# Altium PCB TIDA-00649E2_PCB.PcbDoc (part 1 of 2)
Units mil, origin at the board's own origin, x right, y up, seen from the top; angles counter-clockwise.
Board outline 3905 x 2600 mil, 2 copper layers (Top Layer, Bottom Layer), stack 62 mil thick; 120 components, 45 nets, 260 pads, 117 vias.
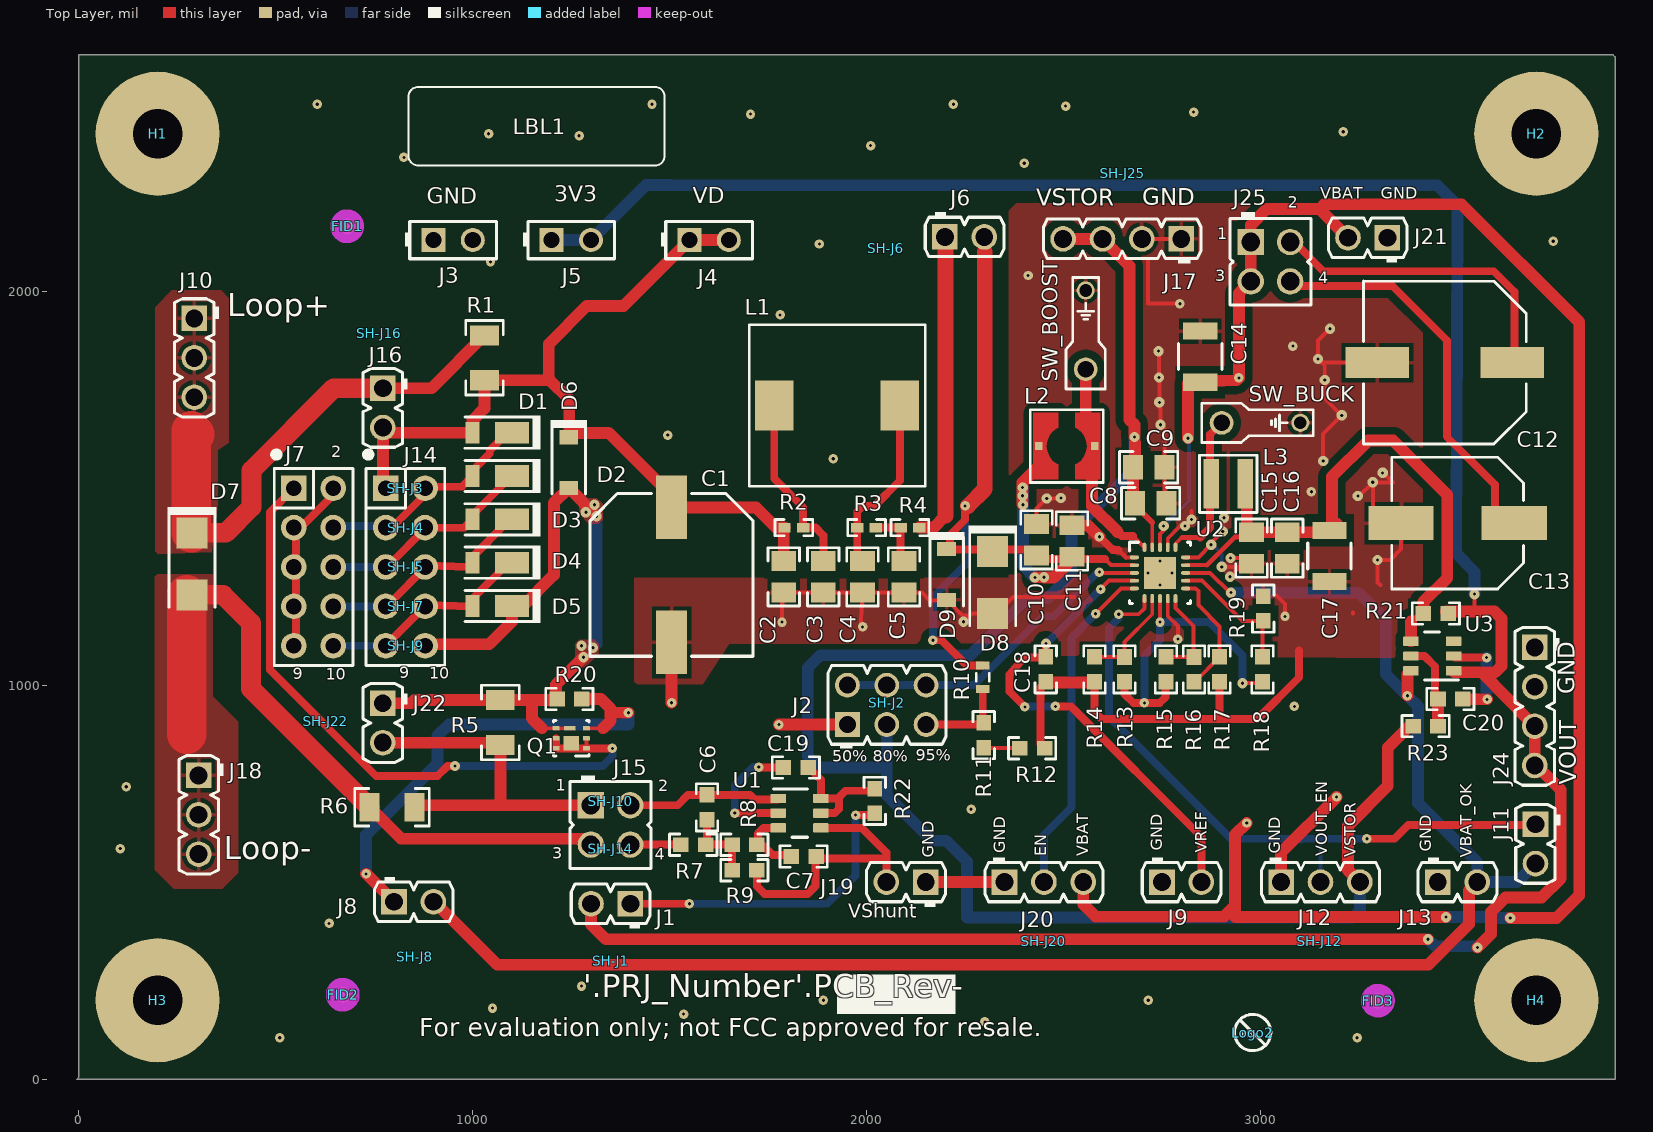
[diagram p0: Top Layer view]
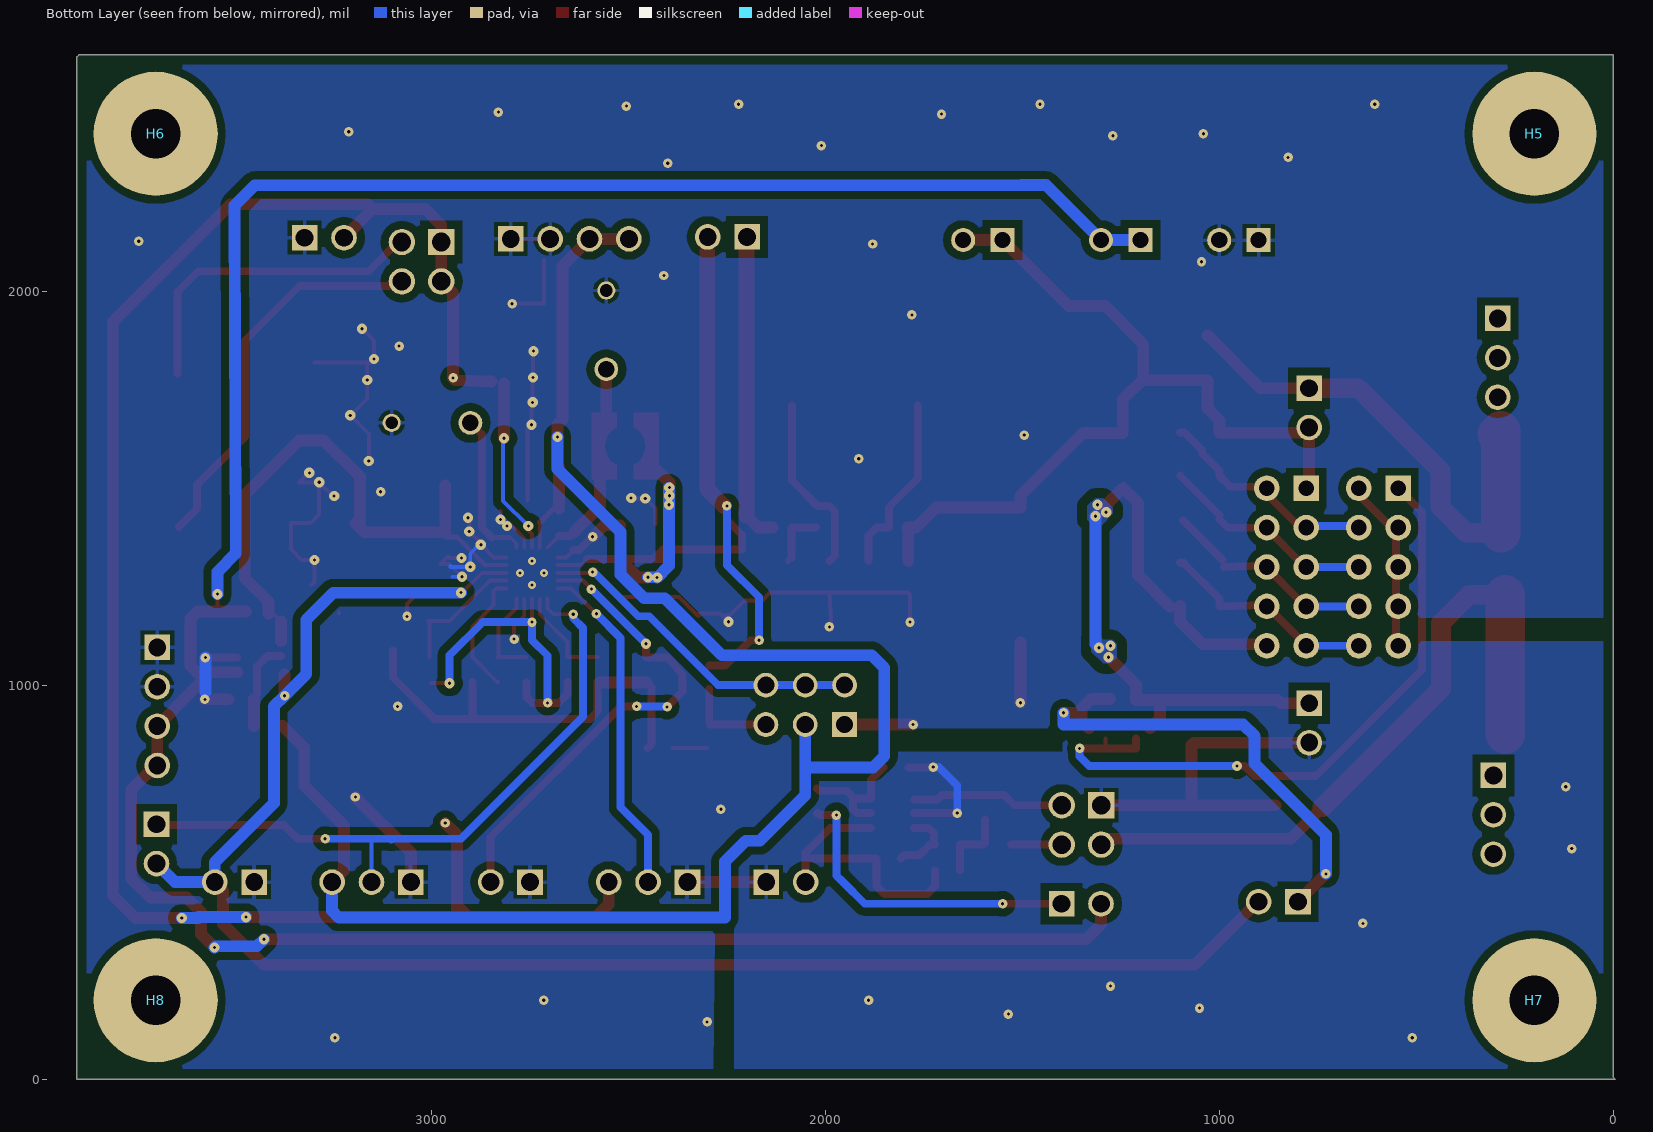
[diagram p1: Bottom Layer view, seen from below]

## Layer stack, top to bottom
Top Solder: solder mask 0.4, Solder Resist, Dk 3.5
Top Layer: signal copper 1.4
Dielectric1: core 59.2, FR-4, Dk 4.8
Bottom Layer: signal copper 1.4
Bottom Solder: solder mask 0.4, Solder Resist, Dk 3.5

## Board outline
-5,0 3900,0 3900,2595 3895,2600 0,2600 0,5 -5,0

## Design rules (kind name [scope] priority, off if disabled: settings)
AcuteAngle [All] p1: minimum=4.50000000000000E+0001 checktracksonly=FALSE
AssemblyTestPointUsage [All] p1: valid=2
BoardOutlineClearance BoardOutlineClearance_MountingHoles [OnCopper and InComponentClass('Mounting Holes')] p1: gap=40
BoardOutlineClearance BoardOutlineClearance_Poly [OnCopper and IsPoly] p2: gap=25
BoardOutlineClearance [OnCopper and Not InComponentClass('Logo') and not InComponentClass('FiducialMark') and not InRegion(1000,500,4000,800) and not InPoly] p3: gap=75
Clearance Clearance_Keepouts [((IsTrack Or IsArc) And Not InPoly) And IsFree and IsKeepOut vs ((IsTrack Or IsArc) And Not InPoly) And IsFree and IsKeepOut] p1: gap=0
Clearance Clearance_Poly [InPolygon] p2: gap=25 except(20: Track-Poly SMDPad-Poly THPad-Poly Via-Poly)
Clearance [All] p3: gap=7.87
ComponentClearance ComponentClearance_MountingHoles_FiducialMarks [InComponentClass('Mounting Holes') vs InComponentClass('FiducialMark')] p1: gap=50 collisioncheckmode=3 verticalgap=10 showdistances=FALSE
ComponentClearance ComponentClearance_Shunt [InComponentClass('Header') OR InComponentClass('Shunt') vs InComponentClass('Shunt')] p2: gap=0 collisioncheckmode=3 verticalgap=0 showdistances=FALSE
ComponentClearance ComponentClearance_Logo [InComponentClass('Logo')] p3: gap=50 collisioncheckmode=3 verticalgap=10 showdistances=FALSE
ComponentClearance ComponentClearance_ScrewToNut [(HasFootprint('NY PMS 440 0025 PH')) vs (HasFootprint('Keystone_1902C'))] p4: gap=5 collisioncheckmode=3 verticalgap=10 showdistances=FALSE
ComponentClearance ComponentClearance_MountingHoles [InComponentClass('Mounting Holes')] p5: gap=100 collisioncheckmode=3 verticalgap=10 showdistances=FALSE
ComponentClearance ComponentClearance_SmallPassives [HasFootprint('0201*') or HasFootprint('0402*') or HasFootprint('0508') or HasFootprint('0603*') or HasFootprint('0612') or HasFootprint('0805*') or HasFootprint('0815*') or HasFootprint('0830*') or HasFootprint('1206*') or HasFootprint('1210*') or HasFootprint('1808*') or HasFootprint('1812*') or HasFootprint('1825*') or HasFootprint('2010*') or HasFootprint('2220*') or HasFootprint('2225*') or HasFootprint('2512*') or HasFootprint('2728*') or HasFootprint('3518*') vs HasFootprint('0201*') or HasFootprint('0402*') or HasFootprint('0508') or HasFootprint('0603*') or HasFootprint('0612') or HasFootprint('0805*') or HasFootprint('0815*') or HasFootprint('0830*') or HasFootprint('1206*') or HasFootprint('1210*') or HasFootprint('1808*') or HasFootprint('1812*') or HasFootprint('1825*') or HasFootprint('2010*') or HasFootprint('2220*') or HasFootprint('2225*') or HasFootprint('2512*') or HasFootprint('2728*') or HasFootprint('3518*')] p6: gap=14.96 collisioncheckmode=3 verticalgap=10 showdistances=FALSE
ComponentClearance ComponentClearance_THtoSMT [IsThruComponent vs IsSMTComponent] p7: gap=0 collisioncheckmode=3 verticalgap=0 showdistances=FALSE
ComponentClearance ComponentClearance_THtoTH [IsThruComponent vs IsThruComponent] p8: gap=0 collisioncheckmode=3 verticalgap=0 showdistances=FALSE
ComponentClearance [All] p9: gap=0 collisioncheckmode=3 verticalgap=0 showdistances=FALSE
DiffPairsRouting [All] p1: maxlimit=100 minlimit=10 mostfreqgap=10 toplayer_minwidth=15 toplayer_maxwidth=15 toplayer_prefwidth=15 bottomlayer_minwidth=15 bottomlayer_maxwidth=15 bottomlayer_prefwidth=15 maxuncoupledlength=1000
FabricationTestPointUsage TestPointUsage [All] p1: valid=2 allowmultiple=FALSE
FabricationTestpoint Testpoint [All] p1: side=3 testpointundercomponent=TRUE minsize=40 maxsize=100 preferedsize=60 minholesize=0 maxholesize=40 preferedholesize=32 testpointgrid=1 allowsidetop=TRUE allowsidebottom=TRUE usegrid=TRUE gridtolerance=0.01
FanoutControl Fanout_LCC [IsLCC] p1: bgadir=Out bgaviamode=Centered fanoutstyle=Auto fanoutdirection=Alternating viagrid=1 // Fanout_LCC (Default Rule)
FanoutControl Fanout_BGA [IsBGA] p2: bgadir=Out bgaviamode=Centered fanoutstyle=Auto fanoutdirection=Alternating viagrid=1 // Fanout_BGA (Default Rule)
FanoutControl Fanout_Default [All] p4: bgadir=Out bgaviamode=Centered fanoutstyle=Auto fanoutdirection=Alternating viagrid=1 // Fanout_Default (Default Rule)
FanoutControl Fanout_Small [(CompPinCount < 5)] p5: bgadir=Out bgaviamode=Centered fanoutstyle=Auto fanoutdirection=OutThenIn viagrid=1 // Fanout_Small (Default Rule)
HoleSize [All] p1: absolutevalues=TRUE maxlimit=251 minlimit=7.87 maxpercent=80.000 minpercent=20.000
MinimumAnnularRing MinimumAnnularRing_ThermalPadVias [IsVia and InAnyComponent] p1: minimumring=5.91
MinimumAnnularRing [All] p2: minimumring=8
MinimumSolderMaskSliver MinimumSolderMaskSliver_Logo [InComponentClass('Logo') vs InComponentClass('Logo')] p1: minsoldermaskwidth=0.7
MinimumSolderMaskSliver [All] p2: minsoldermaskwidth=3.94
PlaneConnect [All] p1: planeconnectstyle=Direct reliefexpansion=10 reliefentries=4 reliefconductorwidth=10 reliefairgap=10
PolygonConnect PolygonConnect_2 [HasFootprint('SMA')] p1: connectstyle=Direct reliefconductorwidth=10 reliefentries=4 polygonreliefangle="90 Angle" airgapwidth=10
PolygonConnect PolygonConnect_1_via [isvia] p2: connectstyle=Direct reliefconductorwidth=10 reliefentries=4 polygonreliefangle="90 Angle" airgapwidth=10
PolygonConnect PolygonConnect_1 [All] p3: connectstyle=Relief reliefconductorwidth=10 reliefentries=4 polygonreliefangle="90 Angle" airgapwidth=10
PolygonConnect [InNet('LOOP +')] p4: connectstyle=Relief reliefconductorwidth=30 reliefentries=4 polygonreliefangle="90 Angle" airgapwidth=10
RoutingVias ThermalPadVias [IsVia and InAnyComponent] p1: holewidth=7.87 width=19.68 viastyle="Through Hole" minholewidth=7.87 minwidth=19.68 maxholewidth=12.99 maxwidth=23.62
RoutingVias [All] p2: holewidth=8 width=24 viastyle="Through Hole" minholewidth=8 minwidth=24 maxholewidth=40 maxwidth=65
SilkToBoardRegionClearance [Not ((IsComment or IsDesignator) And (Hide <> 'False')) and not InRegion(1000,500,4000,800)] p1:
SilkToSilkClearance SilkToSilkClearance_Pb-FreeLogo [(HasFootprint('Pb-Free_Overlay_Medium') OR HasFootprint('Pb-Free_Overlay_Small')) vs (HasFootprint('Pb-Free_Overlay_Medium') OR HasFootprint('Pb-Free_Overlay_Small'))] p1: silktosilkclearance=0
SilkToSilkClearance [All] p2: silktosilkclearance=4
SilkToSolderMaskClearance SilkToComponentPadClearance [IsPad and InAnycomponent] p1: minsilkscreentomaskgap=5 clearancetoexposedcopper=TRUE
SilkToSolderMaskClearance "Silk to Solder Mask Opening" [All] p2: minsilkscreentomaskgap=4 clearancetoexposedcopper=FALSE
SolderMaskExpansion [All] p1: expansion=1.97
Width [All] p1: maxlimit=100 minlimit=6 preferedwidth=10 checkconnectedcopper=TRUE
15 further rules are at their usual default settings.

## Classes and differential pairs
component class TIDA-00649E2_Boost: C8 C9 C10 C11 C12 C13 C14 C15 C16 C17 C18 C20 D8 D9 J2 J6 J9 J11 J12 J13 J17 J20 J21 J24 J25 L2 L3 R10 R11 R12 R13 R14 R15 R16 R17 R18 R19 R21 R23 SH-J2 SH-J6 SH-J12 SH-J20 SH-J25 SW_BOOST SW_BUCK U2 U3
component class Header: J1 J2 J6 J7 J8 J9 J10 J11 J12 J13 J14 J15 J16 J17 J18 J19 J20 J21 J22 J24 J25
component class "Mounting Holes": H1 H2 H3 H4
component class TIDA-00649E2_EVM_Hardware: FID1 FID2 FID3 H1 H2 H3 H4 H5 H6 H7 H8 LBL1 Logo2 Logo3 ZZ1 ZZ2 ZZ3 ZZ4 ZZ5
component class FiducialMark: FID1 FID2 FID3
component class AssemblyNote: ZZ1 ZZ2 ZZ3 ZZ4 ZZ5
component class Label: LBL1
component class TIDA-00649E2_DiodeVoltage: C1 C2 C3 C4 C5 C6 C7 C19 D1 D2 D3 D4 D5 D6 D7 J1 J3 J4 J5 J7 J8 J10 J14 J15 J16 J18 J19 J22 L1 Q1 R1 R2 R3 R4 R5 R6 R7 R8 R9 R20 R22 SH-J1 SH-J3 SH-J4 SH-J5 SH-J7 SH-J8 SH-J9 SH-J10 SH-J14 SH-J16 SH-J22 U1

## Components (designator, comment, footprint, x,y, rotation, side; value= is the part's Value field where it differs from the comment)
C1 "EEEFPE561UAP" Panasonic_G 1504.68,1280 r270 top
C2 "GRM21BR60J107M" 0805_HV 1789.68,1275 r270 top
C3 "GRM21BR61A106KE19L" 0805_HV 1889.68,1275 r270 top
C4 "GRM21BR61A106KE19L" 0805_HV 1989.68,1275 r270 top
C5 "GRM21BR61A106KE19L" 0805_HV 2094.68,1275 r270 top
C6 "C0603C102J5GAC" 0603 1594.68,690 r270 top
C7 "C0603C151J5GACTU" 0603 1840,565 r180 top
C8 "C0805C104K4RACTU" 0805_HV 2721,1462 r0 top
C9 "LMK212B7475KG-T" 0805_HV 2716,1553 r0 top
C10 "C0805C475K8PACTU" 0805_HV 2431,1369 r90 top
C11 "C0805C104K4RACTU" 0805_HV 2521,1366 r90 top
C12 "EEE-FC1A102P" SM_RADIAL_G 3468,1819 r180 top
C13 "APXE100ARA221MH70G" CAPSMT_62_H70 3501,1412 r180 top
C14 "C1210C107M8PACTU" 1210_280 2847,1834 r270 top
C15 "JMK212BJ226MG-T" 0805_HV 2977,1348 r270 top
C16 "GRM21BR71A475KA73L" 0805_HV 3068,1348 r270 top
C17 "C1210C107M8PACTU" 1210_280 3175,1328 r90 top
C18 "GRM188R71H103KA01D" 0603 2454.68,1040 r270 top
C19 "885012206046" 0603 1820.13,791.14 r0 top
C20 "885012206046" 0603 3482,965 r0 top
D1 "DFLS1200-7" PowerDI123 1049.68,1641 r180 top
D2 "DFLU1200-7" PowerDI123 1049.68,1531 r180 top
D3 "DFLU1200-7" PowerDI123 1049.68,1421 r180 top
D4 "DFLU1200-7" PowerDI123 1049.68,1311 r180 top
D5 "DFLU1200-7" PowerDI123 1049.68,1201 r180 top
D6 "1N5819HW-7-F" SOD-123 1243.68,1565 r270 top
D7 "SMAJ5.0A-TR" SMA 287,1308 r270 top
D8 "SMAJ5.0A-TR" SMA 2320,1261 r270 top
D9 "1N5819HW-7-F" SOD-123 2203,1281 r270 top
FID1 "Fiducial" Fiducial10-20 681,2165 r0 top
FID2 "Fiducial" Fiducial10-20 670,214 r0 top
FID3 "Fiducial" Fiducial10-20 3298,199 r0 top
H1 "NY PMS 440 0025 PH" "NY PMS 440 0025 PH" 200,2400 r0 top locked
H2 "NY PMS 440 0025 PH" "NY PMS 440 0025 PH" 3700,2400 r0 top locked
H3 "NY PMS 440 0025 PH" "NY PMS 440 0025 PH" 200,200 r0 top locked
H4 "NY PMS 440 0025 PH" "NY PMS 440 0025 PH" 3700,200 r0 top locked
H5 "1902C" Keystone_1902C 200,2400 r180 bottom locked
H6 "1902C" Keystone_1902C 3700,2400 r180 bottom locked
H7 "1902C" Keystone_1902C 200,200 r180 bottom locked
H8 "1902C" Keystone_1902C 3700,200 r180 bottom locked
J1 "61300211121" WURTH_61300211121 1350,445 r180 top
J2 "61300621121" Wurth_61300621121 2050.98,950 r90 top
J3 "SSW-102-01-T-S" Samtec_SSW-102-01-x-S 950,2130 r0 top
J4 "SSW-102-01-T-S" Samtec_SSW-102-01-x-S 1600,2130 r0 top
J5 "SSW-102-01-T-S" Samtec_SSW-102-01-x-S 1250,2130 r0 top
J6 "61300211121" WURTH_61300211121 2248.68,2138 r0 top
J7 "PEC05DAAN" CONN_PEC05DAAN 595.68,1300 r270 top
J8 "61300211121" WURTH_61300211121 850,450 r0 top
J9 "61300211121" WURTH_61300211121 2799.68,500 r0 top
J10 "61300311121" WURTH_61300311121 293,1831 r270 top
J11 "61300211121" WURTH_61300211121 3698,597 r270 top
J12 "61300311121" WURTH_61300311121 3152.2,500 r0 top
J13 "61300211121" WURTH_61300211121 3500,500 r0 top
J14 "PEC05DAAN" CONN_PEC05DAAN 829,1300 r270 top
J15 "PBC02DAAN" Sullins_PxC02DAAN 1349.68,645 r0 top
J16 "61300211121" WURTH_61300211121 771.68,1704 r270 top
J17 "61300411121" WURTH_61300411121 2648.68,2133 r180 top
J18 "61300311121" WURTH_61300311121 304,671 r270 top
J19 "61300211121" WURTH_61300211121 2100,500 r180 top
J20 "61300311121" WURTH_61300311121 2450,500 r0 top
J21 "61300211121" WURTH_61300211121 3272,2136 r180 top
J22 "61300211121" WURTH_61300211121 771.37,904 r270 top
J24 "61300411121" WURTH_61300411121 3696,946 r270 top
J25 "PBC02DAAN" Sullins_PxC02DAAN 3025,2075 r0 top
L1 "SLF10145T-152MR22-PF" SLF10145 1924.68,1710 r0 top
L2 "744031220" WE-TPC-S 2508,1607 r0 top
L3 "744029100" WE-TPC_2813 2918,1511 r0 top
LBL1 "Size: 0.65\" x 0.20 \"" Label_650x200 1162,2419 r0 top
Logo2 "Pb-Free Symbol" Pb-Free_Overlay_Small 2980,118 r0 top
Logo3 "FCC disclaimer" FCC_disclaimer 2495,3410 r0 top
Q1 "CSD17313Q2" DQK0006C 1250,865 r180 top
R1 "CRCW120610R0FKEA" 1206 1029.68,1831 r90 top
R2 "CRCW04023R32FKED" 0402 1815,1400 r0 top
R3 "CRCW04023R32FKED" 0402 1999.68,1400 r0 top
R4 "CRCW04023R32FKED" 0402 2109.68,1400 r0 top
R5 "CRCW120610R0FKEA" 1206 1070,905 r90 top
R6 "CRCW120610R0FKEA" 1206 795,690 r0 top
R7 "RC0603FR-075K76L" 0603 1559.68,595 r0 top
R8 "CRCW06035K23FKEA" 0603 1689.68,595 r0 top
R9 "CRCW060357K6FKEA" 0603 1689.68,530 r0 top
R10 "CRCW06031M02FKEA" 0603S 2294.68,1020 r270 top
R11 "CRCW060310M0FKEA" 0603 2297,873 r90 top
R12 "CRCW06038M87FKEA" 0603 2420,840 r0 top
R13 "CRCW06037M50FKEA" 0603 2654.68,1040 r90 top
R14 "CRCW06035M76FKEA" 0603 2578.18,1040 r270 top
R15 "CRCW060373K2FKEA" 0603 2760,1040 r270 top
R16 "CRCW06037M68FKEA" 0603 2831.19,1040 r90 top
R17 "CRCW06034M42FKEA" 0603 2896,1040 r90 top
R18 "CRCW06038M25FKEA" 0603 3005,1040 r270 top
R19 "CRCW06034M75FKEA" 0603 3007,1194.5 r270 top
R20 "CRCW06031M00FKEA" 0603 1245.31,965 r0 top
R21 "MCR03EZPJ000" 0603 3445,1182 r0 top
R22 "CRCW060310R0FKEA" 0603 2020.73,705.98 r270 top
R23 "CRCW060310R0FKEA" 0603 3419,896 r0 top
SH-J1 "60900213421" Wurth_60900213421 1350,300 r0 top
SH-J2 "60900213421" Wurth_60900213421 2050.98,955 r90 top
SH-J3 "60900213421" Wurth_60900213421 829,1500 r0 top
SH-J4 "60900213421" Wurth_60900213421 830,1400 r0 top
SH-J5 "60900213421" Wurth_60900213421 830,1300 r0 top
SH-J6 "60900213421" Wurth_60900213421 2049,2109 r90 top
SH-J7 "60900213421" Wurth_60900213421 830,1200 r0 top
SH-J8 "60900213421" Wurth_60900213421 853,311 r0 top
SH-J9 "60900213421" Wurth_60900213421 830,1100 r0 top
SH-J10 "60900213421" Wurth_60900213421 1349.68,705 r0 top
SH-J12 "60900213421" Wurth_60900213421 3150,350 r0 top
SH-J14 "60900213421" Wurth_60900213421 1350,585 r0 top
SH-J16 "60900213421" Wurth_60900213421 762,1894 r0 top
SH-J20 "60900213421" Wurth_60900213421 2450,350 r0 top
SH-J22 "60900213421" Wurth_60900213421 627,909 r270 top
SH-J25 "60900213421" Wurth_60900213421 2650,2300 r0 top
SW_BOOST "TESTPOINT_PIGTAIL" TESTPOINT_PIGTAIL 2556,1802 r180 top
SW_BUCK "TESTPOINT_PIGTAIL" TESTPOINT_PIGTAIL 2901,1666 r90 top
U1 "TLV341AIDBVR" DBV0006A_N 1829.68,675 r0 top
U2 "BQ25570RGRR" RGR0020A 2744.68,1285 r0 top
U3 "TS5A3160DBVR" DBV0006A_N 3436,1074 r180 top
ZZ1 "This Assembly Note is for PCB labels only" AssemblyNoteLabel 245,3498 r0 top
ZZ2 "These assemblies are ESD sensitive, ESD precautions shall be observed." AssemblyNote 245,3389.11 r0 top
ZZ3 "These assemblies must be clean and free from flux and all contaminants. Use of no clean flux is not acceptable." AssemblyNote 245,3300.56 r0 top
ZZ4 "These assemblies must comply with workmanship standards IPC-A-610 Class 2, unless otherwise specified." AssemblyNote 245,3212 r0 top
ZZ5 "Place SH-J1 to J1 Pins 1-2" AssemblyNote 250,3100 r0 top

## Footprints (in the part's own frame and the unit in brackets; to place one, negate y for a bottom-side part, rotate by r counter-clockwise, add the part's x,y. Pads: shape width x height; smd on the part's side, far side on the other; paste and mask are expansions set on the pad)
0402 [mm] "0402 from SM-752 data"
  rect 0.8x0.6 smd: 1(-0.6,0) 2(0.6,0)
  silkscreen extent -1.22,-0.52 1.22,0.52, body extent -0.55,-0.3 0.55,0.3, height 0.6
0603 [mm] "0603 from SM-752 data"
  rect 1x0.95 smd: 1(-0.8,0) 2(0.8,0)
  silkscreen extent -1.52,-0.69 1.52,0.69, body extent -0.87,-0.47 0.87,0.47, height 1
0603S [mil]
  rect 20x35 smd: 1(-30,0) 2(30,0)
  silkscreen extent -10,-17 10,17, body extent -34,-19 34,19, height 39
0805_HV [mil] "0805 with 30mil clearance between pads"
  rect 50x63 smd: 1(-40,0) 2(40,0)
  silkscreen extent -74,-40 74,40, body extent -43,-29 43,29, height 57
1206 [mm] "1206 from SM-752 data"
  rect 1.3x1.85 smd: 1(-1.45,0) 2(1.45,0)
  silkscreen extent -2.4,-1.21 2.4,1.21, body extent -1.7,-0.9 1.7,0.9, height 1.35
1210_280 [mm] "SMD, 2-Leads, Body 3.6x2.8mm, Height 2.8mm"
  rect 1.1x2.2 smd: 1(-1.65,0) 2(1.65,0)
  silkscreen extent -0.84,-1.4 0.84,1.4, body extent -1.8,-1.4 1.8,1.4, height 2.8
AssemblyNote [mil] "Assembly Note"
AssemblyNoteLabel [mil] "Assembly Note for PCB Labels"
CAPSMT_62_H70 [mm] "8 x 6.7mm:  Chemi-Con H70"
  rect 4.2x2.2 smd: 1(-3.638,0.012) 2(3.662,0.012)
  silkscreen extent -4.24,-4.24 4.26,4.26, body extent -4.24,-4.24 4.26,4.26, height 7
CONN_PEC05DAAN [mm] "SULLINS"
  rect 1.65x1.65 hole 1.016 mask+0: 1(-5.08,-1.27)
  round 1.65 hole 1.016 mask+0: 2(-5.08,1.27) 3(-2.54,-1.27) 4(-2.54,1.27) 5(0,-1.27) 6(0,1.27) 7(2.54,-1.27) 8(2.54,1.27) 9(5.08,-1.27) 10(5.08,1.27)
  silkscreen extent -7.45,-2.6 6.35,2.54, body extent -6.35,-2.54 6.35,2.54, height 8.38
DBV0006A_N [mm] "SOT23, 6-Leads, Body 2.9x1.6mm, Pitch 0.95mm, Lead Span 2.8mm, IPC Medium Density"
  rrect17% 1x0.6 smd: 1(-1.375,0.95) 2(-1.375,0) 3(-1.375,-0.95) 4(1.375,-0.95) 5(1.375,0) 6(1.375,0.95)
  silkscreen extent -1.68,-1.55 0.5,1.55, body extent -1.42,-1.46 1.42,1.46, height 1.12
DQK0006C [mm] "WSON"
  rrect12% 0.9x0.86 on Top Paste: 0(0,0.325)
  rrect34% 0.7x0.29 on Top Paste: 0(0.095,-0.65)
  rrect33% 0.45x0.3 smd: 1(-0.975,0.65) 2(-0.975,0) 3(-0.975,-0.65) 4(0.975,-0.65) 5(0.975,0) 6(0.975,0.65)
  rrect33% 0.75x0.3 smd paste-0.15: 7(0.095,-0.65)
  rrect11% 1x0.95 smd paste-0.5: 8(0,0.325)
  silkscreen extent -1.15,-1.15 1.15,1.15, body extent -1,-1 1,1, height 0.82
FCC_disclaimer [mil]
Fiducial10-20 [mm]
  round 1 smd mask+0.5: 1(0,0)
  Top Layer keep-out circle w1.178: c0,0 r0.5
Keystone_1902C [mil] "Hex Standoff, 4-40 threaded, nylon"
  body extent -145,-126 146,126, height 501
Label_650x200 [mil] "Thermal Transfer Label"
  silkscreen extent -325,-100 325,100, body extent -325,-100 325,100, height 1
"NY PMS 440 0025 PH" [mm] "4-40 nylon screw and mounting hole"
  round 8 hole 3.2: 1(0,0)
  body extent -3.3,-3.3 3.3,3.3, height 2.69
Panasonic_G [mm] "SMD, 2-Leads, Dia 10mm"
  rect 4.1x2 smd: 1(-4.35,0) 2(4.35,0)
  silkscreen extent -5.25,-5.25 5.25,5.25, body extent -5.25,-5.25 5.25,5.25, height 10.51
Pb-Free_Overlay_Small [mil]
  silkscreen extent -46,-46 46,46
PowerDI123 [mm] "Diodes Inc recommended land pattern, document number DS30628 Rev. 6-2"
  rect 2.2x1.4 smd: 1(-1.275,0)
  rect 0.9x1.4 smd: 2(1.275,0)
  silkscreen extent -3.1,-1.09 1.76,1.09, body extent -2.38,-0.97 1.52,0.96, height 1
RGR0020A [mm] "QFN, 20-Leads, Body 3.5x3.5mm, Pitch 0.5mm, Thermal Pad 2.05x2.05mm, TI Recommended"
  oval 0.6x0.24 smd: 1(-1.65,1) 2(-1.65,0.5) 3(-1.65,0) 4(-1.65,-0.5) 5(-1.65,-1) 11(1.65,-1) 12(1.65,-0.5) 13(1.65,0) 14(1.65,0.5) 15(1.65,1)
  oval 0.24x0.6 smd: 6(-1,-1.65) 7(-0.5,-1.65) 8(0,-1.65) 9(0.5,-1.65) 10(1,-1.65) 16(1,1.65) 17(0.5,1.65) 18(0,1.65) 19(-0.5,1.65) 20(-1,1.65)
  rect 2.05x2.05 smd paste-1.025: 21(0,0)
  silkscreen extent -1.97,-1.97 1.97,1.97, body extent -1.83,-1.83 1.83,1.83, height 1.01
Samtec_SSW-102-01-x-S [mm] "Receptacle, 2x1, 2.54mm, TH"
  rect 1.55x1.55 hole 1.04: 1(-1.27,0)
  round 1.55 hole 1.04: 2(1.27,0)
  silkscreen extent -3.1,-1.21 2.79,1.21, body extent -2.79,-1.21 2.8,1.2, height 8.51
SLF10145 [mm]
  rect 2.5x3.2 smd: 1(-4.05,0) 2(4.05,0)
  silkscreen extent -5.66,-5.2 5.7,5.2, body extent -5.2,-5.2 5.2,5.2, height 4.8
SM_RADIAL_G [mm] "10 x 10.2mm:  Panasonic G"
  rect 4.1x2 smd: 1(-4.35,0) 2(4.35,0)
  silkscreen extent -5.25,-5.25 5.25,5.25, body extent -5.25,-5.25 5.25,5.25, height 10.5
SMA [mm] "Molded Diode, 2-Leads, Body 4.3x2.6mm, IPC Medium Density, based on OnSemi component dimensions and land pattern"
  rect 2x2 smd: 1(-2,0) 2(2,0)
  silkscreen extent -3.66,-1.57 2.79,1.57, body extent -2.6,-1.3 2.6,1.3, height 2.42
SOD-123 [mm] "On Semi recommended land pattern"
  rect 0.915x1.22 smd: 1(-1.637,0) 2(1.637,0)
  silkscreen extent -2.74,-1.17 2.03,1.17, body extent -1.93,-0.9 1.93,0.9, height 1.35
Sullins_PxC02DAAN [mm] "Header, 2.54mm, 2x2, TH"
  rect 1.7x1.7 hole 1.2: 1(-1.27,1.27)
  round 1.7 hole 1.2: 2(1.27,1.27) 3(-1.27,-1.27) 4(1.27,-1.27)
  silkscreen extent -2.61,-2.8 2.61,3.2, body extent -2.61,-2.8 2.61,2.8, height 8.58
TESTPOINT_PIGTAIL [mil] "Pigtail"
  round 60 hole 42: 1(0,0)
  round 46 hole 32: 2(0,-200)
  silkscreen extent -50,-233 50,50
WE-TPC-S [mm] "Wurth Elektronik recommended land pattern"
  rect 0.5x0.5 smd: 1(-1.8,0) 2(1.8,0)
  Top Layer region: -0.55,1.185 -0.658,1.14 -0.931,0.931 -1.14,0.658 -1.271,0.341 -1.316,0 -1.271,-0.341 -1.14,-0.658 -0.931,-0.931 -0.658,-1.14 -0.55,-1.185 -0.55,-2.15 -2.15,-2.15 -2.15,2.15 -0.55,2.15
  Top Layer region: 2.15,-2.15 0.55,-2.15 0.55,-1.185 0.658,-1.14 0.931,-0.931 1.14,-0.658 1.271,-0.341 1.316,0 1.271,0.341 1.14,0.658 0.931,0.931 0.658,1.14 0.55,1.185 0.55,2.15 2.15,2.15
  silkscreen extent -2.35,-2.35 2.35,2.35, body extent -2.05,-2.05 2.05,2.05, height 1.8
WE-TPC_2813 [mm] "Wurth Elektronik recommended land pattern"
  rect 1x3.2 smd: 1(-1.1,0) 2(1.1,0)
  silkscreen extent -1.85,-1.85 1.85,1.85, body extent -1.5,-1.5 1.5,1.5, height 1.5
Wurth_60900213421 [mil] "Shunt, 2.54mm, Black"
  round 1 on Mech3: 0(0,0)
  body extent -98,-48 98,48, height 236
WURTH_61300211121 [mm] "Header, 2.54mm, 2x1, TH"
  rect 1.65x1.65 hole 1.15: 1(-1.27,0)
  round 1.65 hole 1.15: 2(1.27,0)
  silkscreen extent -2.54,-1.27 2.54,1.6, body extent -2.54,-1.27 2.54,1.27, height 8.54
WURTH_61300311121 [mm] "Header, 2.54mm, 3x1, TH"
  rect 1.65x1.65 hole 1.15: 1(-2.54,0)
  round 1.65 hole 1.15: 2(0,0) 3(2.54,0)
  silkscreen extent -3.81,-1.27 3.81,1.6, body extent -3.81,-1.27 3.81,1.27, height 8.54
WURTH_61300411121 [mm] "Header, 2.54mm, 4x1, TH"
  rect 1.65x1.65 hole 1.15: 1(-3.81,0)
  round 1.65 hole 1.15: 2(-1.27,0) 3(1.27,0) 4(3.81,0)
  silkscreen extent -5.08,-1.27 5.08,1.6, body extent -5.08,-1.27 5.08,1.27, height 8.54
Wurth_61300621121 [mm] "Header, 2.54mm, 3x2, TH"
  rect 1.6x1.6 hole 1.1: 1(-1.27,2.54)
  round 1.6 hole 1.1: 2(1.27,2.54) 3(-1.27,0) 4(1.27,0) 5(-1.27,-2.54) 6(1.27,-2.54)
  silkscreen extent -2.8,-3.82 2.54,3.8, body extent -2.54,-3.82 2.54,3.8, height 7.27

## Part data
C1: "CAP, AL, 560 µF, 25 V, +/- 20%, 0.08 ohm, AEC-Q200 Grade 2, SMD"
C2: "CAP, CERM, 100 µF, 6.3 V, +/- 20%, X5R, 0805"
C3 C4 C5: "CAP, CERM, 10 µF, 10 V, +/- 10%, X5R, 0805"
C6: "CAP, CERM, 1000 pF, 50 V, +/- 5%, C0G/NP0, 0603"
C7: "CAP, CERM, 150 pF, 50 V, +/- 5%, C0G/NP0, 0603"
C8 C11: "CAP, CERM, 0.1 µF, 16 V, +/- 10%, X7R, 0805"
C9 C16: "CAP, CERM, 4.7 µF, 10 V, +/- 10%, X7R, 0805"
C10: "CAP, CERM, 4.7 µF, 10 V, +/- 10%, X5R, 0805"
C12: "CAP, AL, 1000 µF, 10 V, +/- 20%, 0.15 ohm, SMD"
C13: "CAP, AL, 220 µF, 10 V, +/- 20%, 0.021 ohm, SMD"
C14 C17: "CAP, CERM, 100 µF, 10 V, +/- 20%, X5R, 1210"
C15: "CAP, CERM, 22 µF, 6.3 V, +/- 20%, X5R, 0805"
C18: "CAP, CERM, 0.01 µF, 50 V, +/- 10%, X7R, 0603"
C19 C20: "CAP, CERM, 0.1 µF, 16 V, +/- 10%, X7R, 0603"
D1: "Diode, Schottky, 200 V, 1 A, PowerDI123"
D2 D3 D4 D5: "Diode, Superfast Rectifier, 200 V, 1 A, AEC-Q101, PowerDI123"
D6 D9: "Diode, Schottky, 40 V, 1 A, SOD-123"
D7 D8: "Diode, TVS, Uni, 5 V, 13.4 Vc, SMA"
FID1 FID2 FID3: "Fiducial mark.  There is nothing to buy or mount."
H1 H2 H3 H4: "Machine Screw, Round, #4-40 x 1/4, Nylon, Philips panhead"
H5 H6 H7 H8: "Standoff, Hex, 0.5\"L #4-40 Nylon"
J1 J6 J8 J9 J11 J13 J16 J19 J21 J22: "Header, 2.54 mm, 2x1, Gold, TH"
J2: "Header, 2.54mm, 3x2, Gold, TH"
J3 J4 J5: "Receptacle, 2x1, 2.54mm, Tin, TH"
J7 J14: "Header, 100mil, 5x2, Tin, TH"
J10 J12 J18 J20: "Header, 2.54 mm, 3x1, Gold, TH"
J15 J25: "Header, 2.54mm, 2x2, Gold, TH"
J17 J24: "Header, 2.54 mm, 4x1, Gold, TH"
L1: "Inductor, Shielded Drum Core, Ferrite, 1.5 mH, 0.22 A, 3.4 ohm, SMD"
L2: "Inductor, Shielded Drum Core, Ferrite, 22 µH, 0.36 A, 0.41 ohm, SMD"
L3: "Inductor, Shielded Drum Core, Ferrite, 10 µH, 0.5 A, 0.39 ohm, SMD"
LBL1: library part THT-14-423-10, "Thermal Transfer Printable Labels, 0.650\" W x 0.200\" H - 10,000 per roll"
Logo2: library part Pb-Free
Logo3: library part FCC_disclaimer, "FCC_disclaimer"
Q1: "MOSFET, N-CH, 30 V, 5 A, DQK0006C (WSON-6)"
R1 R5 R6: "RES, 10.0, 1%, 0.25 W, 1206"
R2 R3 R4: "RES, 3.32, 1%, 0.063 W, 0402"
R7: "RES, 5.76 k, 1%, 0.1 W, 0603"
R8: "RES, 5.23 k, 1%, 0.1 W, 0603"
R9: "RES, 57.6 k, 1%, 0.1 W, 0603"
R10: "RES, 1.02 M, 1%, 0.1 W, 0603"
R11: "RES, 10.0 M, 1%, 0.1 W, 0603"
R12: "RES, 8.87 M, 1%, 0.1 W, 0603"
R13: "RES, 7.50 M, 1%, 0.1 W, 0603"
R14: "RES, 5.76 M, 1%, 0.1 W, 0603"
R15: "RES, 73.2 k, 1%, 0.1 W, 0603"
R16: "RES, 7.68 M, 1%, 0.1 W, 0603"
R17: "RES, 4.42 M, 1%, 0.1 W, 0603"
R18: "RES, 8.25 M, 1%, 0.1 W, 0603"
R19: "RES, 4.75 M, 1%, 0.1 W, 0603"
R20: "RES, 1.00 M, 1%, 0.1 W, 0603"
R21: "RES, 0, 5%, 0.1 W, 0603"
R22 R23: "RES, 10.0, 1%, 0.1 W, 0603"
SH-J1 SH-J2 SH-J3 SH-J4 SH-J5 SH-J6 SH-J7 SH-J8 SH-J9 SH-J10 SH-J12 SH-J14 SH-J16 SH-J20 SH-J22 SH-J25: "Shunt, 2.54mm, Gold, Black"
SW_BOOST SW_BUCK: "PIGTAIL"
U1: "Low-Voltage, Rail-To-Rail Output CMOS Operational Amplifier with Shutdown, 1.5 to 5.5 V, -40 to 125 degC, 6-pin SOT23 (DBV0006A), Green (RoHS & no Sb/Br)"
U2: "Ultra Low Power Harvester Power Management IC with Boost Charger, and Nano-Powered Buck Converter, RGR0020A"
U3: "1-Ohm SPDT ANALOG SWITCH 5-V/3.3-V SINGLE-CHANNEL 2:1 MULTIPLEXER/DEMULTIPLEXER, DBV0006A"
ZZ1: library part AssemblyNoteLabel
ZZ2 ZZ3 ZZ4 ZZ5: library part AssemblyNote

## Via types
v1: diameter 24, hole 8, Top Layer to Bottom Layer, tented both sides, 66 vias
v2: diameter 26, hole 8, Top Layer to Bottom Layer, tented both sides, 47 vias
v3: diameter 19.68, hole 7.87, Top Layer to Bottom Layer, 4 vias

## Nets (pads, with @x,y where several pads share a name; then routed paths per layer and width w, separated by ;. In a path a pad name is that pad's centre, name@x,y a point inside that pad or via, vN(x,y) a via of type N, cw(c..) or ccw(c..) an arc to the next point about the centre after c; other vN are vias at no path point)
3.3VDC: J1.1 R22.2 | length 805.8
  Top Layer w20: J1.1@1400,445 v1(1550,445) ; v1(1972,670) 2015.21,670 2020.21,675 R22.2@2020.73,674.49
  Bottom Layer w20: v1(1550,445) 1900,445 1955,500 1972,517 v1(1972,670)
3V3: J1.2 J5.1 J5.2 J24.3 J24.4 R21.2 U3.1 | length 7140.6
  Top Layer w10: 3543,1190 v2(3543,1231)
  Top Layer w30: J1.2@1300,445 1300,393 1338,355 v2(3425,355) ; R21.2@3470.5,1187 3594,1187 3612,1169 3612,1049 3596,1033 3491.94,1033 3562.59,1031.69 3685,907 J24.3@3696,896 3696,800.32 3762,734.32 3762,509 3714,461 3622,461 3585,424 3585,368 v2(3551,334)
  Bottom Layer w30: J5.1@1200,2130 J5.2@1300,2130 1439.65,2269.65 1502,2269.65 3449,2269 3499.66,2218.34 3496.66,1334.65 3543,1288 v2(3543,1231) ; v2(3425,355) 3443,337 3548,337 v2(3551,334)
3V3_1: C15.1 C16.1 C17.2 L3.2 R21.1 U2.14 U3.4 | length 1479.9
  Top Layer w10: U2.14@2809.65,1304.68 2863.68,1304.68 ; C15.1@2965,1388 C15.1@2977,1388 ; C17.2@3170.04,1388 C17.2@3175,1392.96 ; 3381.87,1161.36 R21.1@3407.5,1187
  Top Layer w12: 2863.68,1304.68 2935,1376 2965,1376 C15.1@2977,1388
  Top Layer w30: C15.1@2965,1388 L3.2@2965,1507.31 ; C15.1@2977,1388 C16.1@3068,1388 C17.2@3170.04,1388 ; C17.2@3175,1392.96 C17.2@3193,1410.96 ; C17.2@3181,1408.96 3181,1529 3273,1621 3337,1621 3474,1484 3474,1272 3413.5,1211.5 R21.1@3413.5,1182 ; U3.4@3381.87,1111.4 3381.87,1161.36
DJ2: D1.1 D2.2 J7.4 J14.2 J14.3 | length 556.7
  Top Layer w20: J14.3@774.37,1407 802,1407 898.63,1503.63 972.12,1503.63 D2.2@999.49,1531 999.49,1544.49 1043,1588 1043,1596 1088,1641 D1.1@1099.88,1641
  Bottom Layer w20: J7.4@649.68,1404 J14.3@771.37,1404
DJ3: D2.1 D3.2 J7.6 J14.4 J14.5 | length 531.1
  Top Layer w20: J14.5@779.05,1307 789,1307 881.38,1399.38 978.49,1400 D3.2@999.49,1421 ; D3.2@998.49,1431.61 D2.1@1098.88,1532
  Bottom Layer w20: J7.6@645.68,1300 J14.5@767.37,1300
DJ4: D3.1 D4.2 J7.8 J14.6 J14.7 | length 517.8
  Top Layer w20: J14.7@774.37,1207 788,1207 884.55,1303.55 D4.2@988.49,1300 ; D4.2@991.49,1318 D3.1@1091.88,1418.39
  Bottom Layer w20: J7.8@645.68,1200 J14.7@767.37,1200
DJ5: D4.1 D5.2 J7.10 J14.8 J14.9 | length 544.1
  Top Layer w20: J14.9@774.37,1107 785,1107 881.67,1203.67 998.49,1200 D5.2@999.49,1201 999.49,1219.49 1091,1311 D4.1@1099.88,1311
  Bottom Layer w20: J7.10@645.68,1100 J14.9@767.37,1100
DJT: D5.1 D6.2 J14.10 J22.1 Q1.4 Q1.7 R5.2 R20.1 | length 1812.9
  Top Layer w10: 1175.59,890.59 Q1.4@1211.62,890.59 Q1.7@1246.26,890.59
  Top Layer w30: J22.1@771.37,954 844,954 852.09,962.09 R5.2@1070,962.09 1150,962.09 ; J14.10@871.37,1104 1042,1104 1099.88,1161.88 D5.1@1099.88,1201 ; D5.1@1125,1199 1206,1280 1206,1462.85 D6.2@1243.68,1500.53 ; 1175.59,890.59 1150,916.19 1150,962.09 ; D6.2@1244.68,1499.53 1314,1430.22 v2(1314,1429) ; v2(1281,1071) 1210.91,1000.91 1210.91,962.09 1150,962.09
  Bottom Layer w30: v2(1305,1095) 1314,1104 v2(1314,1429)
  other v2: 1276,1100 1287,1439 1309.1,1458
EN: J20.2 U2.5 | length 860.8
  Top Layer w10: v1(2581.1,1181.1) 2645.63,1245.63 U2.5@2679.72,1245.63
  Bottom Layer w20: J20.2@2450,500 2450,620 2520,690 2520,1120 v1(2581.1,1181.1)
GND: C1.2 C2.2 C3.2 C4.2 C5.2 C8.2 C9.2 C10.2 C11.2 C12.2 C13.2 C14.1 C15.2 C16.2 C17.1 C18.2 C19.1 C20.2 D8.2 D9.2 J2.1 J3.1 J3.2 J9.1 J12.1 J13.1 J15.1 J17.1 J17.2 J19.1 J20.1 J21.1 J22.2 J24.1 J24.2 R5.1 R6.2 R12.2 R14.2 R17.1 R19.1 SW_BOOST.2 SW_BUCK.2 U1.2 U2.1 U2.9 U2.15 U2.17 U2.21 U3.2 | length 7169.3
  Top Layer w10: R6.2@852.09,690 R6.2@857.09,695 ; v1@1725.14,791.14 v1(1726,792) ; v1(1785,1160) C2.2@1785,1230.31 ; C2.2@1789.68,1235 C3.2@1889.68,1235 C4.2@1989.68,1235 ; v1@1984.68,1143 C4.2@1989.68,1235 ; v2(2246,1161) 2262.26,1177.26 ; D8.2@2320,1177.26 2325,1177.26 2371.74,1224 2528,1224 ; D8.2@2320,1182.26 2267.26,1182.26 2262.26,1177.26 ; C10.2@2431,1409 2431,1448 v2(2457,1474) 2492,1474 v2(2493,1475) ; C18.2@2441,994.82 2453.19,1007.01 C18.2@2454.68,1008.5 ; R12.2@2445,846.5 R12.2@2451.5,840 ; 2657.63,1324.37 U2.1@2679.72,1324.37 ; J17.2@2698.68,2133 J17.2@2728.69,2133 ; J17.2@2713.69,2118 J17.2@2728.69,2133 ; 2714.69,2080 2714.69,1968.5 v1(2795.28,1968.5) ; v2(2741,1848) 2742,1847 v2(2742,1781) 2743,1780 v2(2743,1718) 2743,1705 2746,1702 v2(2746,1661) 2756,1651 C9.2@2756,1553 ; C8.2@2756.31,1469 C9.2@2756.31,1564 ; U2.9@2764.37,1220.04 2764.37,1175.63 2790,1150 v1(2790,1117) ; U2.17@2764.37,1349.96 2764.37,1372.37 2796,1404 v2(2808,1404) ; J17.1@2798.68,2133 J17.2@2728.69,2133 ; U2.15@2809.65,1324.37 2842.37,1324.37 v2(2874.56,1356.56) 2874.56,1360.56 v2(2904,1390) 2904,1422 v2(2907,1425) ; v2(2824.58,1420.58) 2824.58,1442.42 ; v2(2901.42,1300.42) C15.2@2946.42,1300.42 ; v2(2922.5,1275.18) 2955.32,1308 C15.2@2977,1308 2958,1327 2954.06,1323.06 v2(2924,1323.06) ; 3040.5,1228 3062,1206.5 v1(3062,1174.5) ; v1@3085.04,946.04 v1(3085.96,946.04) ; v2(3159,1569) 3159,1638 v2(3206,1685) 3163,1728 v2(3163,1775) 3163,1811 v2@3155,1819 ; v2(3176,1905) 3146,1875 v2(3146,1828) v2@3155,1819 ; 3235.03,1182.33 3235.03,1185.03 ; v2(3247,1480) 3250,1480 v2(3285,1515) ; C12.2@3296.74,1819 v2@3155,1819 ; 3304,1254 3296.87,1261.13 v2(3296.87,1318.06) 3329.69,1318.06 3356.81,1345.19 C13.2@3356.81,1411.51 3306.49,1411.51 3285,1433 v2(3285,1515) ; v2(3310,1539) 3312,1539 3336,1515 v2(3285,1515) ; U3.2@3490.13,1074 U3.2@3494.13,1070 ; C4.2@1989.68,1235 C5.2@2094.68,1235 2140,1235 2160,1215 2205.53,1215 2243.27,1177.26 2262.26,1177.26
  Top Layer w12: 2639,1343 2657.63,1324.37
  Top Layer w20: v1(1665,675) 1725,675 U1.2@1775.55,675 ; v1@1725.14,791.14 C19.1@1788.64,791.14 ; C18.2@2441,994.82 2441,850.5 R12.2@2451.5,840 ; R14.2@2578.18,1008.5 2578.18,932.82 2597,914 2992,914 3098,1020 3098,1088 ; v1(2591,1376.86) 2624.86,1343 2639,1343 ; 2896,926 R17.1@2896,1008.5 ; U3.2@3494.13,1070 v1(3574,1070)
  Top Layer w30: J22.2@771.37,854 R5.1@1063.91,854 ; R6.2@857.09,695 1071,695 ; R5.1@1070,847.91 1070,696 1071,695 ; J15.1@1299.68,695 1071,695 ; v1(1504.68,955.32) C1.2@1504.68,1108.74 ; v1(1777.17,900) J2.1@1950.98,900 ; J19.1@2150,500 J20.1@2350,500 ; C18.2@2453.19,1007.01 R14.2@2571.69,1007.01 ; C11.2@2521,1406 2561.86,1406 v1(2591,1376.86) ; J12.1@3052.2,500 3052.2,575.2 v1(3193,716) ; C20.2@3514.5,964 v1(3575,964)
  Bottom Layer w10: 1712,792 v1(1726,792) ; v2@2878.44,1356.56 2901.42,1333.58 v2(2901.42,1300.42) 2951.58,1300.42 2951.58,1303.11 ; v2(2922.5,1275.18) 2947.18,1275.18 ; v1@3569,964 v1(3575,964) 3575,981 3574,982
  Bottom Layer w20: v1(1665,675) 1665,745 1712,792
  Bottom Layer w30: 3574,982 v1(3574,1070)
  other v1: 510,105 3245,105 2300,145 1535,165 1050,180 1890,200 2715,200 1276,236 635,395 105,585 2265,685 120,742 1989.68,1148 3129,1491 1915,1575 1495,1635 3082,1861 1780,1940 2410,2040 1045,2075 1880,2120 3743,2127 2400,2325 825,2340 2010,2370 1270,2395 1040,2400 3210,2405 1705,2450 2830,2455 2505,2470 605,2475 1455,2475 2220,2475
  other v3: 2744.68,1254.49 2714.17,1285 2775.2,1285 2744.68,1315.51
"LOOP +": D7.1 J10.1 J10.2 J10.3 J16.1 R1.2 | length 1278.8
  Top Layer w10: D7.1@285,1386.74 D7.1@308.26,1386.74
  Top Layer w30: J16.1@771.68,1754 895.6,1754 R1.2@1029.68,1888.09
  Top Layer w50: D7.1@308.26,1386.74 372.74,1386.74 438,1452 438,1545 647,1754 J16.1@771.68,1754
  Top Layer w100: D7.1@285,1386.74 285,1646 294,1637
LOOP-: D7.2 J15.3 J18.1 J18.2 J18.3 R6.1 | length 1740.5
  Top Layer w10: J15.3@1284.68,610 J15.3@1299.68,595
  Top Layer w30: R6.1@737.91,690 817.91,610 J15.3@1284.68,610
  Top Layer w50: D7.2@274,1229.26 365.74,1229.26 437,1158 437,990.91 R6.1@737.91,690
  Top Layer w100: 274,875 D7.2@274,1229.26
NetC3_1: C3.1 L1.1 R2.2 | length 464.7
  Top Layer w20: L1.1@1765.24,1710 1765.24,1524.76 1838.62,1451.38 R2.2@1838.62,1400 1870,1400 1890,1380 C3.1@1890,1315.31
NetC4_1: C4.1 L1.2 R3.1 | length 463
  Top Layer w20: C4.1@1989.68,1315 1976.06,1328.62 R3.1@1976.06,1400 1976.06,1441.06 1990,1455 2020,1455 2084.13,1519.13 L1.2@2084.13,1710
NetC5_1: C5.1 R3.2 R4.1 | length 151.3
  Top Layer w15: C5.1@2086.06,1323.62 C5.1@2094.68,1315
  Top Layer w20: R3.2@2023.31,1400 R4.1@2086.06,1400 2086.06,1364.06 C5.1@2086.06,1323.62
